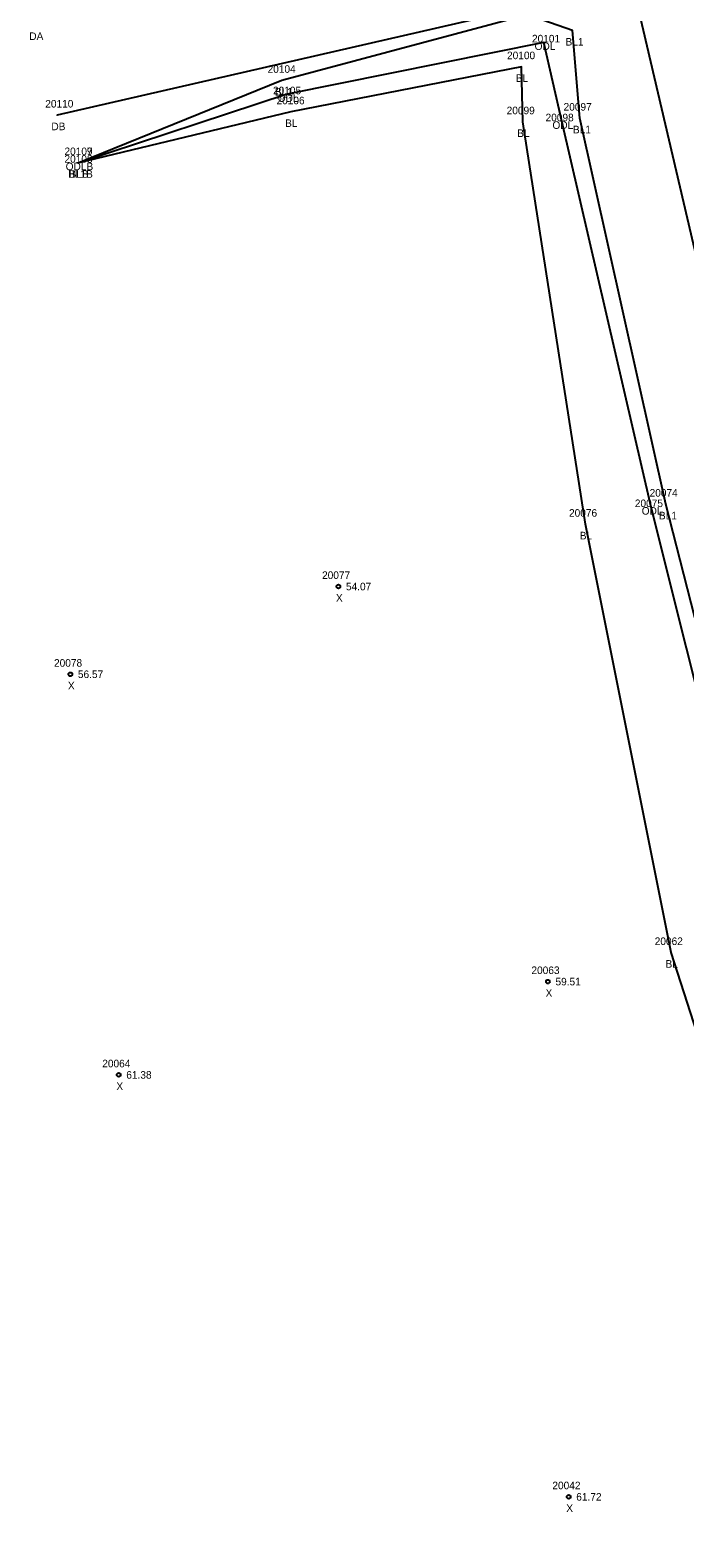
# Model space of a CAD drawing. Extents: x 2445178 to 2446260, y 791158 to 792318.
# Drawn here: x 2445664.3 to 2445750.9, y 791354.3 to 791553.6 of the extents above; entities that cross this region are included whole.
import ezdxf

# ---------------------------------------------------------------- set-up
doc = ezdxf.new("R2010")
doc.units = 0
for name, color, linetype in [('RD_DTM_BkLn1', 7, 'Continuous'), ('RD_EX_Driveway', 7, 'Continuous'), ('RD_EX_Driveway_txCode', 7, 'Continuous'), ('RD_EX_H2O', 7, 'Continuous'), ('RD_EX_H2O_txCode', 7, 'Continuous'), ('RD_EX_Road', 7, 'Continuous'), ('RD_Sketch8', 7, 'Continuous'), ('RD_SMD_Locator', 7, 'Continuous'), ('RD_SMD_Misc', 7, 'Continuous')]:
    doc.layers.add(name, color=color, linetype=linetype)

msp = doc.modelspace()

# ---------------------------------------------------------------- linework, layer by layer
at = {"layer": 'RD_DTM_BkLn1'}
for points in [[(2445839.71, 791171.21), (2445812.99, 791261.63), (2445797.26, 791317.94), (2445780.39, 791374.8), (2445762.73, 791434.98), (2445748.42, 791490.93), (2445737.04, 791541.96), (2445736.07, 791553.56), (2445730.12, 791555.63), (2445697.6, 791546.96), (2445670.73, 791536.08)], [(2445828.38, 791169.47), (2445802.46, 791258.37), (2445786.04, 791313.32), (2445768.83, 791370.56), (2445749.12, 791431.66), (2445737.78, 791488.28), (2445729.51, 791541.48), (2445729.31, 791548.76), (2445698.8, 791542.8), (2445670.73, 791536.08)]]:
    msp.add_lwpolyline(points, dxfattribs=at)
at = {"layer": 'RD_EX_Driveway'}
msp.add_line((2445744.01, 791559.83), (2445667.9, 791542.37), dxfattribs=at)
at = {"layer": 'RD_EX_H2O'}
msp.add_lwpolyline([(2445837.89, 791170.92), (2445811.42, 791261.06), (2445795.3, 791316.79), (2445777.82, 791373.49), (2445760.55, 791434.46), (2445746.47, 791490.55), (2445734.66, 791541.55), (2445732.29, 791551.98), (2445698.31, 791545.12), (2445670.73, 791536.08)], dxfattribs=at)
at = {"layer": 'RD_EX_Road'}
msp.add_lwpolyline([(2445850.42, 791174.36), (2445823.13, 791264.7), (2445806.34, 791321.46), (2445789.41, 791379.89), (2445773.46, 791437.57), (2445759.36, 791494.22), (2445744.01, 791559.83), (2445740.09, 791577.64), (2445731.05, 791621.01), (2445722.21, 791669.43), (2445711, 791738.26), (2445706.49, 791765.2)], dxfattribs=at)
at = {"layer": 'RD_SMD_Locator'}
for centre, radius in [((2445736.07, 791553.56), 0.001), ((2445732.29, 791551.98), 0.001), ((2445729.31, 791548.76), 0.001), ((2445697.6, 791546.96), 0.001), ((2445698.31, 791545.12), 0.001), ((2445667.9, 791542.37), 0.001), ((2445698.8, 791542.8), 0.001), ((2445729.51, 791541.48), 0.001), ((2445734.66, 791541.55), 0.001), ((2445737.04, 791541.96), 0.001), ((2445670.73, 791536.08), 0.001), ((2445670.73, 791536.08), 0.001), ((2445670.73, 791536.08), 0.001), ((2445746.47, 791490.55), 0.001), ((2445748.42, 791490.93), 0.001), ((2445737.78, 791488.28), 0.001), ((2445705.09, 791480.05), 0.25), ((2445669.63, 791468.45), 0.25), ((2445749.12, 791431.66), 0.001), ((2445732.81, 791427.82), 0.25), ((2445676.03, 791415.49), 0.25), ((2445735.56, 791359.71), 0.25)]:
    msp.add_circle(centre, radius, dxfattribs=at)

# ---------------------------------------------------------------- texts
at = {"layer": 'RD_EX_Driveway_txCode'}
for s, p in [('DA', (2445664.2, 791552.3)), ('20110', (2445666.31, 791543.37)), ('DB', (2445667.12, 791540.37))]:
    msp.add_text(s, height=1, dxfattribs=at).set_placement(p)
at = {"layer": 'RD_EX_H2O_txCode'}
for s, p in [('20101', (2445730.7, 791551.98)), ('ODL', (2445731.05, 791550.98)), ('20105', (2445696.44, 791545.12)), ('ODL', (2445697.07, 791544.12)), ('20098', (2445732.5, 791541.55)), ('ODL', (2445733.41, 791540.55)), ('20108', (2445668.85, 791536.08)), ('ODLB', (2445669.01, 791535.08)), ('20075', (2445744.31, 791490.55)), ('ODL', (2445745.22, 791489.55))]:
    msp.add_text(s, height=1, dxfattribs=at).set_placement(p)
at = {"layer": 'RD_Sketch8'}
for s, p in [('20077', (2445702.93, 791481.05)), ('54.07', (2445706.09, 791479.55)), ('X', (2445704.77, 791478.05)), ('20078', (2445667.47, 791469.45)), ('56.57', (2445670.63, 791467.95)), ('X', (2445669.31, 791466.45)), ('20063', (2445730.63, 791428.82)), ('59.51', (2445733.81, 791427.32)), ('X', (2445732.5, 791425.82)), ('20064', (2445673.85, 791416.49)), ('61.38', (2445677.03, 791414.99)), ('X', (2445675.72, 791413.49)), ('20042', (2445733.4, 791360.71)), ('61.72', (2445736.56, 791359.21)), ('X', (2445735.24, 791357.71))]:
    msp.add_text(s, height=1, dxfattribs=at).set_placement(p)
at = {"layer": 'RD_SMD_Misc'}
for s, p in [('BL1', (2445735.14, 791551.56)), ('20100', (2445727.4, 791549.76)), ('20104', (2445695.72, 791547.96)), ('BL', (2445728.56, 791546.76)), ('BL1', (2445696.68, 791544.96)), ('20106', (2445696.9, 791543.8)), ('20099', (2445727.35, 791542.48)), ('20097', (2445734.88, 791542.96)), ('BL', (2445698.04, 791540.8)), ('BL', (2445728.75, 791539.48)), ('BL1', (2445736.12, 791539.96)), ('20107', (2445668.85, 791537.08)), ('20109', (2445668.85, 791537.08)), ('BL1B', (2445669.33, 791534.08)), ('BLB', (2445669.5, 791534.08)), ('20074', (2445746.26, 791491.93)), ('20076', (2445735.6, 791489.28)), ('BL1', (2445747.5, 791488.93)), ('BL', (2445737.02, 791486.28)), ('20062', (2445746.94, 791432.66)), ('BL', (2445748.37, 791429.66))]:
    msp.add_text(s, height=1, dxfattribs=at).set_placement(p)

doc.saveas('drawing.dxf')
